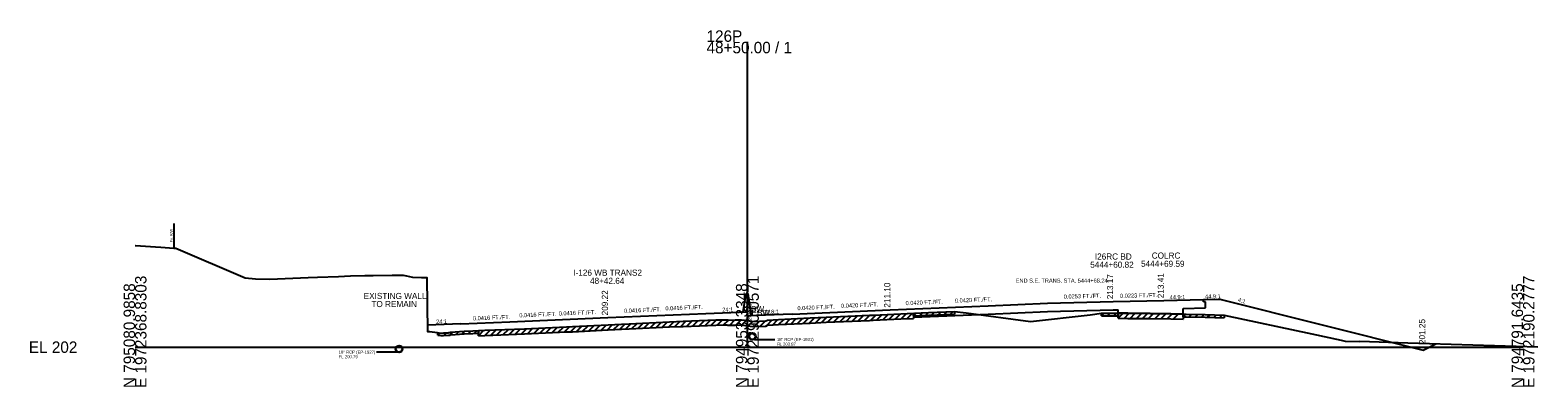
# Model space of a CAD drawing. Extents: x -161 to 1970889, y -4362 to 797231.
# Drawn here: x 1974.3 to 2343.6, y 990.3 to 1077.5 of the extents above; entities that cross this region are included whole.
import ezdxf

# ---------------------------------------------------------------- set-up
doc = ezdxf.new("R2010")
doc.units = 0
for name, color, linetype in [('RD_GPK_XS_Cell', 7, 'Continuous'), ('RD_XS_Base', 7, 'Continuous'), ('RD_XS_EarthShd', 7, 'Continuous'), ('RD_XS_ExGround', 7, 'Continuous'), ('RD_XS_ExPaveRet', 7, 'Continuous'), ('RD_XS_ExRW', 7, 'Continuous'), ('RD_XS_MedBWall', 7, 'Continuous'), ('RD_XS_Misc_Line', 7, 'Continuous'), ('RD_XS_Pave', 7, 'Continuous'), ('RD_XS_PaveOvlay', 7, 'Continuous'), ('RD_XS_PaveShd', 7, 'Continuous'), ('RD_XS_Pipe', 7, 'Continuous'), ('RD_XS_TieSlope', 7, 'Continuous'), ('RD_XS_TX_Elev_EX', 7, 'Continuous'), ('RD_XS_TX_Elev_PR', 7, 'Continuous'), ('RD_XS_TX_Misc', 7, 'Continuous'), ('RD_XS_TX_MkPT', 7, 'Continuous'), ('RD_XS_TX_Notes', 7, 'Continuous'), ('RD_XS_TX_Profile', 7, 'Continuous'), ('RD_XS_TX_ShdSlope', 7, 'Continuous'), ('RD_XS_TX_Slope', 7, 'Continuous'), ('RD_XS_TX_Station', 7, 'Continuous')]:
    doc.layers.add(name, color=color, linetype=linetype)

msp = doc.modelspace()

# ---------------------------------------------------------------- linework, layer by layer
at = {"layer": 'RD_GPK_XS_Cell'}
for p, q in [((2150, 1000), (2150, 1074.67)), ((2000, 1000), (2150, 1000)), ((2150, 1000), (2340, 1000))]:
    msp.add_line(p, q, dxfattribs=at)
at = {"layer": 'RD_XS_Base'}
for p, q in [((2209, 1008.07), (2223.51, 1008.72)), ((2223.51, 1008.72), (2239.59, 1009.13)), ((2239.59, 1009.13), (2240.79, 1009.15)), ((2256.73, 1009.47), (2262.2, 1009.59)), ((2261.7, 1011.06), (2261.7, 1011.62)), ((2262.2, 1011.07), (2261.7, 1011.06)), ((2262.2, 1009.59), (2262.2, 1011.07)), ((2190.72, 1007.3), (2209, 1008.07))]:
    msp.add_line(p, q, dxfattribs=at)
at = {"layer": 'RD_XS_EarthShd'}
msp.add_line((2261.7, 1011.62), (2265.72, 1011.71), dxfattribs=at)
at = {"layer": 'RD_XS_ExGround'}
for p, q in [((2311.81, 1001), (2300, 1001.36)), ((2343.63, 1000), (2311.81, 1001))]:
    msp.add_line(p, q, dxfattribs=at)
msp.add_lwpolyline([(2000, 1024.84), (2000.1, 1024.89), (2004.99, 1024.55), (2006.31, 1024.47), (2009.52, 1024.25), (2010.01, 1024.24), (2026.95, 1016.96), (2029.5, 1016.71), (2033.02, 1016.6), (2042.37, 1017.02), (2044.69, 1017.15), (2049.86, 1017.32), (2052.8, 1017.42), (2056.33, 1017.55), (2057.22, 1017.55), (2058.37, 1017.56), (2062.97, 1017.59), (2064.57, 1017.59), (2065.71, 1017.59), (2066.49, 1017.45), (2067.95, 1017.08), (2070.16, 1017.07), (2070.68, 1017.07), (2071.46, 1017.07), (2071.66, 1003.86), (2072.23, 1003.79), (2074.04, 1003.56), (2074.89, 1003.45), (2075.54, 1003.47), (2076.78, 1003.52), (2076.89, 1003.56), (2077.16, 1003.57), (2077.3, 1003.68), (2080.61, 1003.88), (2082.73, 1004.01), (2085.71, 1004.13), (2095.43, 1004.52), (2105.68, 1004.96), (2107.19, 1005.03), (2115.93, 1005.46), (2119.17, 1005.62), (2121.05, 1005.71), (2130.93, 1006.19), (2134.27, 1006.33), (2142.3, 1006.67), (2144.04, 1006.71), (2144.98, 1006.72), (2145.17, 1006.66), (2145.42, 1006.63), (2147.04, 1006.66), (2148.58, 1006.7), (2150, 1006.48), (2151.35, 1006.27), (2154.51, 1006.41), (2154.91, 1006.6), (2156.29, 1006.68), (2157.63, 1006.76), (2165.38, 1007.14), (2169.3, 1007.33), (2179.95, 1007.79), (2180.78, 1007.82), (2187.56, 1008.14), (2192.6, 1008.38), (2194.35, 1008.46), (2200.72, 1008.74), (2203.57, 1008.38), (2219.32, 1006.25), (2233.98, 1007.93), (2236.75, 1008.29), (2239.52, 1008.31), (2240.64, 1008.32), (2243.22, 1008.3), (2248.69, 1008.24), (2253.72, 1008.14), (2257.51, 1008.06), (2262.14, 1007.95), (2266.79, 1007.83), (2288.28, 1003.25), (2295.47, 1001.74), (2296.44, 1001.49), (2300, 1001.36)], dxfattribs=at)
at = {"layer": 'RD_XS_ExPaveRet'}
for p, q in [((2190.72, 1008.29), (2190.72, 1007.04)), ((2190.72, 1007.67), (2190.72, 1008.29)), ((2200.72, 1008.74), (2200.72, 1008.11)), ((2236.75, 1007.67), (2236.75, 1008.29)), ((2240.79, 1007.06), (2240.79, 1008.31)), ((2240.79, 1008.31), (2240.79, 1007.69)), ((2121.05, 1004.46), (2130.93, 1004.94)), ((2130.93, 1004.94), (2134.27, 1005.08)), ((2134.27, 1005.08), (2142.3, 1005.42)), ((2142.3, 1005.42), (2144.04, 1005.46)), ((2144.04, 1005.46), (2144.98, 1005.47)), ((2144.98, 1005.47), (2145.17, 1005.41)), ((2145.17, 1005.41), (2145.42, 1005.38)), ((2145.42, 1005.38), (2147.04, 1005.41)), ((2147.04, 1005.41), (2148.58, 1005.45)), ((2148.58, 1005.45), (2150, 1005.23)), ((2150, 1005.23), (2151.35, 1005.02)), ((2151.35, 1005.02), (2154.51, 1005.16)), ((2154.51, 1005.16), (2154.91, 1005.35)), ((2154.91, 1005.35), (2156.29, 1005.43)), ((2156.29, 1005.43), (2157.63, 1005.51)), ((2157.63, 1005.51), (2165.38, 1005.89)), ((2165.38, 1005.89), (2169.3, 1006.08)), ((2169.3, 1006.08), (2179.95, 1006.54)), ((2179.95, 1006.54), (2180.78, 1006.57)), ((2180.78, 1006.57), (2187.56, 1006.89)), ((2187.56, 1006.89), (2190.72, 1007.04)), ((2190.72, 1007.67), (2192.6, 1007.75)), ((2192.6, 1007.75), (2194.35, 1007.83)), ((2194.35, 1007.83), (2200.72, 1008.11)), ((2236.75, 1007.67), (2239.52, 1007.69)), ((2239.52, 1007.69), (2240.64, 1007.69)), ((2240.64, 1007.69), (2240.79, 1007.69)), ((2240.79, 1007.06), (2243.22, 1007.05)), ((2243.22, 1007.05), (2248.69, 1006.99)), ((2248.69, 1006.99), (2253.72, 1006.89)), ((2253.72, 1006.89), (2256.73, 1006.83)), ((2256.73, 1008.08), (2256.73, 1006.83)), ((2256.73, 1007.45), (2256.73, 1008.08)), ((2256.73, 1007.45), (2257.51, 1007.44)), ((2257.51, 1007.44), (2262.14, 1007.33)), ((2262.14, 1007.33), (2266.79, 1007.21)), ((2266.79, 1007.83), (2266.79, 1007.21)), ((2074.15, 1002.92), (2074.15, 1003.55)), ((2074.15, 1002.92), (2074.89, 1002.82)), ((2074.89, 1002.82), (2075.54, 1002.85)), ((2075.54, 1002.85), (2076.78, 1002.9)), ((2076.78, 1002.9), (2076.89, 1002.93)), ((2076.89, 1002.93), (2077.16, 1002.94)), ((2077.16, 1002.94), (2077.3, 1003.05)), ((2077.3, 1003.05), (2080.61, 1003.25)), ((2080.61, 1003.25), (2082.73, 1003.38)), ((2082.73, 1003.38), (2084.15, 1003.44)), ((2084.15, 1002.81), (2084.15, 1004.06)), ((2084.15, 1004.06), (2084.15, 1003.44)), ((2084.15, 1002.81), (2085.71, 1002.88)), ((2085.71, 1002.88), (2095.43, 1003.27)), ((2095.43, 1003.27), (2105.68, 1003.71)), ((2105.68, 1003.71), (2107.19, 1003.78)), ((2107.19, 1003.78), (2115.93, 1004.21)), ((2115.93, 1004.21), (2119.17, 1004.37)), ((2119.17, 1004.37), (2121.05, 1004.46))]:
    msp.add_line(p, q, dxfattribs=at)
at = {"layer": 'RD_XS_ExRW'}
msp.add_line((2009.5, 1030.25), (2009.5, 1024.25), dxfattribs=at)
at = {"layer": 'RD_XS_MedBWall'}
for p, q in [((2149, 1008.6), (2149.67, 1013.14)), ((2150.18, 1013.14), (2149.67, 1013.14)), ((2151, 1007.67), (2150.18, 1013.14))]:
    msp.add_line(p, q, dxfattribs=at)
at = {"layer": 'RD_XS_Misc_Line'}
for p, q in [((2189.16, 1006.97), (2190.47, 1008.28)), ((2190.72, 1007.67), (2191.37, 1008.32)), ((2192.22, 1007.74), (2192.87, 1008.39)), ((2193.72, 1007.8), (2194.37, 1008.46)), ((2195.22, 1007.87), (2195.87, 1008.52)), ((2196.72, 1007.94), (2197.37, 1008.59)), ((2198.22, 1008), (2198.87, 1008.66)), ((2199.72, 1008.07), (2200.37, 1008.72)), ((2236.75, 1007.67), (2237.38, 1008.3)), ((2238.25, 1007.68), (2238.88, 1008.31)), ((2239.75, 1007.69), (2240.38, 1008.32)), ((2240.79, 1007.06), (2242.03, 1008.31)), ((2242.29, 1007.05), (2243.53, 1008.29)), ((2243.79, 1007.04), (2245.03, 1008.28)), ((2245.29, 1007.02), (2246.53, 1008.26)), ((2096.15, 1003.3), (2097.46, 1004.61)), ((2097.65, 1003.37), (2098.96, 1004.67)), ((2099.15, 1003.43), (2100.46, 1004.74)), ((2100.65, 1003.5), (2101.96, 1004.8)), ((2102.15, 1003.56), (2103.46, 1004.87)), ((2103.65, 1003.63), (2104.96, 1004.93)), ((2105.15, 1003.69), (2106.46, 1005)), ((2106.65, 1003.76), (2107.97, 1005.07)), ((2108.15, 1003.83), (2109.47, 1005.14)), ((2109.65, 1003.9), (2110.97, 1005.22)), ((2111.15, 1003.98), (2112.47, 1005.29)), ((2112.65, 1004.05), (2113.97, 1005.36)), ((2114.15, 1004.12), (2115.47, 1005.44)), ((2115.65, 1004.19), (2116.97, 1005.51)), ((2117.15, 1004.27), (2118.47, 1005.58)), ((2118.65, 1004.34), (2119.97, 1005.65)), ((2120.15, 1004.41), (2121.47, 1005.73)), ((2121.65, 1004.49), (2122.97, 1005.8)), ((2123.15, 1004.56), (2124.47, 1005.87)), ((2124.65, 1004.63), (2125.97, 1005.95)), ((2126.15, 1004.71), (2127.47, 1006.02)), ((2127.66, 1004.78), (2128.97, 1006.09)), ((2129.16, 1004.85), (2130.47, 1006.17)), ((2130.66, 1004.93), (2131.96, 1006.23)), ((2132.16, 1004.99), (2133.46, 1006.3)), ((2133.66, 1005.06), (2134.96, 1006.36)), ((2135.16, 1005.12), (2136.46, 1006.42)), ((2136.66, 1005.18), (2137.96, 1006.49)), ((2138.16, 1005.25), (2139.46, 1006.55)), ((2139.66, 1005.31), (2140.96, 1006.61)), ((2141.16, 1005.37), (2142.46, 1006.67)), ((2142.66, 1005.43), (2143.93, 1006.7)), ((2144.16, 1005.46), (2145.34, 1006.64)), ((2145.66, 1005.39), (2146.93, 1006.66)), ((2147.16, 1005.42), (2148.44, 1006.7)), ((2148.66, 1005.44), (2149.74, 1006.52)), ((2150.16, 1005.21), (2151.24, 1006.29)), ((2151.66, 1005.03), (2152.97, 1006.34)), ((2153.16, 1005.1), (2154.47, 1006.41)), ((2154.66, 1005.23), (2156.1, 1006.67)), ((2156.16, 1005.42), (2157.48, 1006.75)), ((2157.66, 1005.51), (2158.97, 1006.82)), ((2159.16, 1005.58), (2160.47, 1006.9)), ((2160.66, 1005.66), (2161.97, 1006.97)), ((2162.16, 1005.73), (2163.47, 1007.05)), ((2163.66, 1005.8), (2164.97, 1007.12)), ((2165.16, 1005.88), (2166.47, 1007.19)), ((2166.66, 1005.95), (2167.97, 1007.26)), ((2168.16, 1006.02), (2169.47, 1007.34)), ((2169.66, 1006.09), (2170.96, 1007.4)), ((2171.16, 1006.16), (2172.46, 1007.46)), ((2172.66, 1006.22), (2173.96, 1007.53)), ((2174.16, 1006.29), (2175.46, 1007.59)), ((2175.66, 1006.35), (2176.96, 1007.66)), ((2177.16, 1006.42), (2178.46, 1007.73)), ((2178.66, 1006.48), (2179.97, 1007.79)), ((2180.16, 1006.55), (2181.47, 1007.86)), ((2181.66, 1006.62), (2182.97, 1007.93)), ((2183.16, 1006.69), (2184.47, 1008)), ((2184.66, 1006.76), (2185.97, 1008.07)), ((2186.16, 1006.83), (2187.47, 1008.14)), ((2187.66, 1006.9), (2188.97, 1008.21)), ((2246.79, 1007.01), (2248.03, 1008.24)), ((2248.29, 1006.99), (2249.52, 1008.22)), ((2249.79, 1006.96), (2251.02, 1008.19)), ((2251.29, 1006.93), (2252.52, 1008.16)), ((2252.79, 1006.91), (2254.02, 1008.13)), ((2254.29, 1006.88), (2255.52, 1008.1)), ((2256.73, 1007.45), (2257.35, 1008.06)), ((2258.23, 1007.42), (2258.84, 1008.03)), ((2259.73, 1007.38), (2260.34, 1008)), ((2261.23, 1007.35), (2261.84, 1007.96)), ((2262.73, 1007.31), (2263.34, 1007.92)), ((2264.23, 1007.27), (2264.84, 1007.88)), ((2265.73, 1007.23), (2266.34, 1007.84)), ((2074.15, 1002.92), (2074.7, 1003.47)), ((2075.65, 1002.85), (2076.3, 1003.5)), ((2077.15, 1002.94), (2077.92, 1003.72)), ((2078.65, 1003.13), (2079.32, 1003.8)), ((2080.15, 1003.23), (2080.82, 1003.89)), ((2081.65, 1003.32), (2082.32, 1003.98)), ((2083.15, 1003.4), (2083.8, 1004.05)), ((2084.15, 1002.81), (2085.46, 1004.12)), ((2085.65, 1002.87), (2086.96, 1004.18)), ((2087.15, 1002.94), (2088.46, 1004.24)), ((2088.65, 1003), (2089.96, 1004.3)), ((2090.15, 1003.06), (2091.46, 1004.36)), ((2091.65, 1003.12), (2092.96, 1004.42)), ((2093.15, 1003.18), (2094.46, 1004.48)), ((2094.65, 1003.24), (2095.96, 1004.54))]:
    msp.add_line(p, q, dxfattribs=at)
at = {"layer": 'RD_XS_Pave'}
for p, q in [((2161, 1008.09), (2185, 1009.1)), ((2185, 1009.1), (2209, 1010.11)), ((2223.51, 1010.76), (2239.59, 1011.17)), ((2239.59, 1011.17), (2252.01, 1011.4)), ((2079.83, 1005.73), (2091.84, 1006.22)), ((2091.84, 1006.22), (2115.84, 1007.22)), ((2115.84, 1007.22), (2139.84, 1008.22))]:
    msp.add_line(p, q, dxfattribs=at)
at = {"layer": 'RD_XS_PaveOvlay'}
for p, q in [((2187.56, 1008.14), (2190.72, 1008.29)), ((2190.72, 1008.29), (2190.72, 1007.3)), ((2240.79, 1008.31), (2240.79, 1009.15)), ((2243.22, 1008.3), (2240.79, 1008.31)), ((2245.95, 1008.27), (2243.22, 1008.3)), ((2248.69, 1008.24), (2245.95, 1008.27)), ((2256.73, 1008.08), (2256.73, 1009.47)), ((2095.43, 1004.52), (2105.68, 1004.96)), ((2105.68, 1004.96), (2107.19, 1005.03)), ((2107.19, 1005.03), (2115.93, 1005.46)), ((2115.93, 1005.46), (2119.17, 1005.62)), ((2119.17, 1005.62), (2121.05, 1005.71)), ((2121.05, 1005.71), (2130.93, 1006.19)), ((2130.93, 1006.19), (2134.27, 1006.33)), ((2134.27, 1006.33), (2142.3, 1006.67)), ((2142.3, 1006.67), (2144.04, 1006.71)), ((2144.04, 1006.71), (2144.98, 1006.72)), ((2144.98, 1006.72), (2145.17, 1006.66)), ((2145.17, 1006.66), (2145.42, 1006.63)), ((2145.42, 1006.63), (2147.04, 1006.66)), ((2147.04, 1006.66), (2148.58, 1006.7)), ((2148.58, 1006.7), (2150, 1006.48)), ((2150, 1006.48), (2151.35, 1006.27)), ((2151.35, 1006.27), (2154.51, 1006.41)), ((2154.51, 1006.41), (2154.91, 1006.6)), ((2154.91, 1006.6), (2156.29, 1006.68)), ((2156.29, 1006.68), (2157.63, 1006.76)), ((2157.63, 1006.76), (2165.38, 1007.14)), ((2165.38, 1007.14), (2169.3, 1007.33)), ((2169.3, 1007.33), (2179.95, 1007.79)), ((2179.95, 1007.79), (2180.78, 1007.82)), ((2180.78, 1007.82), (2187.56, 1008.14)), ((2253.72, 1008.14), (2248.69, 1008.24)), ((2256.73, 1008.08), (2253.72, 1008.14)), ((2084.15, 1004.06), (2085.71, 1004.13)), ((2085.71, 1004.13), (2095.43, 1004.52))]:
    msp.add_line(p, q, dxfattribs=at)
msp.add_lwpolyline([(2071.64, 1005.38), (2071.66, 1003.86), (2072.23, 1003.79), (2074.04, 1003.56), (2074.89, 1003.45), (2075.54, 1003.47), (2076.78, 1003.52), (2076.89, 1003.56), (2077.16, 1003.57), (2077.3, 1003.68), (2080.61, 1003.88), (2082.73, 1004.01), (2084.15, 1004.06)], dxfattribs=at)
at = {"layer": 'RD_XS_PaveShd'}
for p, q in [((2139.84, 1008.22), (2150, 1008.64)), ((2150, 1007.63), (2150, 1008.64)), ((2209, 1010.11), (2223.51, 1010.76)), ((2252.01, 1011.4), (2261.7, 1011.62)), ((2079.83, 1005.73), (2071.64, 1005.38)), ((2161, 1008.09), (2150, 1007.63))]:
    msp.add_line(p, q, dxfattribs=at)
at = {"layer": 'RD_XS_Pipe'}
for p, q in [((2151.73, 1001.87), (2156.73, 1001.87)), ((2064.17, 998.79), (2059.17, 998.79))]:
    msp.add_line(p, q, dxfattribs=at)
for centre, radius in [((2151.23, 1002.62), 0.85), ((2151.23, 1002.62), 0.75), ((2064.67, 999.54), 0.85), ((2064.67, 999.54), 0.75)]:
    msp.add_circle(centre, radius, dxfattribs=at)
at = {"layer": 'RD_XS_TieSlope'}
for p, q in [((2265.72, 1011.71), (2315.55, 999.25)), ((2315.55, 999.25), (2318.61, 1000.79))]:
    msp.add_line(p, q, dxfattribs=at)

# ---------------------------------------------------------------- texts
at = {"layer": 'RD_GPK_XS_Cell'}
for s, p in [('48+50.00 / 1', (2140, 1071.87)), ('126P', (2140, 1074.67)), ('EL 202', (1974, 998.6))]:
    msp.add_text(s, height=2.8, dxfattribs=at).set_placement(p)
for s, p in [('E 1972368.8303', (2002.8, 990)), ('E 1972290.0571', (2152.8, 990)), ('E 1972190.2777', (2342.8, 990)), ('N 795080.9858', (2000, 990)), ('N 794953.3348', (2150, 990)), ('N 794791.6435', (2340, 990))]:
    msp.add_text(s, height=2.8, rotation=90, dxfattribs=at).set_placement(p)
at = {"layer": 'RD_XS_ExRW'}
msp.add_text('Ex. R/W ', height=0.65, rotation=90, dxfattribs=at).set_placement((2009.25, 1025.63))
at = {"layer": 'RD_XS_Pipe'}
for s, p in [('18" RCP (EP-1931)', (2157.22, 1001.5)), ('FL 203.87', (2157.22, 1000.37)), ('18" RCP (EP-1927)', (2049.88, 998.42)), ('FL 200.79', (2049.88, 997.29))]:
    msp.add_text(s, height=0.75, dxfattribs=at).set_placement(p)
at = {"layer": 'RD_XS_TX_Elev_EX'}
msp.add_text('208.48', height=1, rotation=90, dxfattribs=at).set_placement((2151, 1006.48))
at = {"layer": 'RD_XS_TX_Elev_PR'}
for s, p in [(' 211.10', (2185, 1009.1)), (' 213.17', (2239.59, 1011.17)), (' 213.41', (2252.01, 1011.4)), (' 209.22', (2115.84, 1007.22))]:
    msp.add_text(s, height=1.5, rotation=90, dxfattribs=at).set_placement(p)
at = {"layer": 'RD_XS_TX_Misc'}
msp.add_text('201.25', height=1.5, rotation=90, dxfattribs=at).set_placement((2316.03, 1000.75))
at = {"layer": 'RD_XS_TX_MkPT'}
for s, p in [('WBW', (2149, 1008.6)), ('EBW', (2151, 1007.67))]:
    msp.add_text(s, height=1.5, dxfattribs=at).set_placement(p)
at = {"layer": 'RD_XS_TX_Notes'}
for s, height, p in [('END S.E. TRANS. STA. 5444+68.24', 1, (2215.73, 1015.78)), ('EXISTING WALL', 1.5, (2056.01, 1011.77)), ('TO REMAIN', 1.5, (2057.9, 1009.8))]:
    msp.add_text(s, height=height, dxfattribs=at).set_placement(p)
at = {"layer": 'RD_XS_TX_Profile'}
for s, rotation, p in [('24:1', 2.3823, (2143.86, 1008.64)), ('23.8:1', 2.405, (2153.91, 1008.05)), ('24:1', 2.3818, (2073.77, 1005.72))]:
    msp.add_text(s, height=1, rotation=rotation, dxfattribs=at).set_placement(p)
at = {"layer": 'RD_XS_TX_ShdSlope'}
msp.add_text('44.9:1', height=1, rotation=1.2767, dxfattribs=at).set_placement((2262.12, 1011.88))
at = {"layer": 'RD_XS_TX_Slope'}
for s, rotation, p in [('0.0420 FT./FT.', 2.405, (2200.85, 1010.86)), ('0.0253 FT./FT.', 1.4482, (2227.51, 1011.86)), ('0.0223 FT./FT.', 1.2782, (2241.28, 1012.05)), ('44.9:1', 1.2767, (2253.45, 1011.69)), ('4:1', 344.1175, (2270.05, 1011.16)), ('0.0416 FT./FT.', 2.3818, (2094.15, 1007.27)), ('0.0416 FT./FT.', 2.3818, (2103.8, 1007.72)), ('0.0416 FT./FT.', 2.3823, (2119.8, 1008.39)), ('0.0416 FT./FT.', 2.3818, (2129.94, 1008.97)), ('0.0420 FT./FT.', 2.405, (2162.28, 1009.02)), ('0.0420 FT./FT.', 2.405, (2172.96, 1009.6)), ('0.0420 FT./FT.', 2.405, (2188.77, 1010.26)), ('0.0416 FT./FT.', 2.3821, (2082.8, 1006.53))]:
    msp.add_text(s, height=1, rotation=rotation, dxfattribs=at).set_placement(p)
at = {"layer": 'RD_XS_TX_Station'}
for s, p in [('COLRC', (2249.05, 1021.65)), ('5444+60.82', (2233.98, 1019.42)), ('I26RC BD', (2235.12, 1021.42)), ('5444+69.59', (2246.43, 1019.65)), ('I-126 WB TRANS2', (2107.35, 1017.47)), ('48+42.64', (2111.45, 1015.47))]:
    msp.add_text(s, height=1.5, dxfattribs=at).set_placement(p)

doc.saveas('drawing.dxf')
